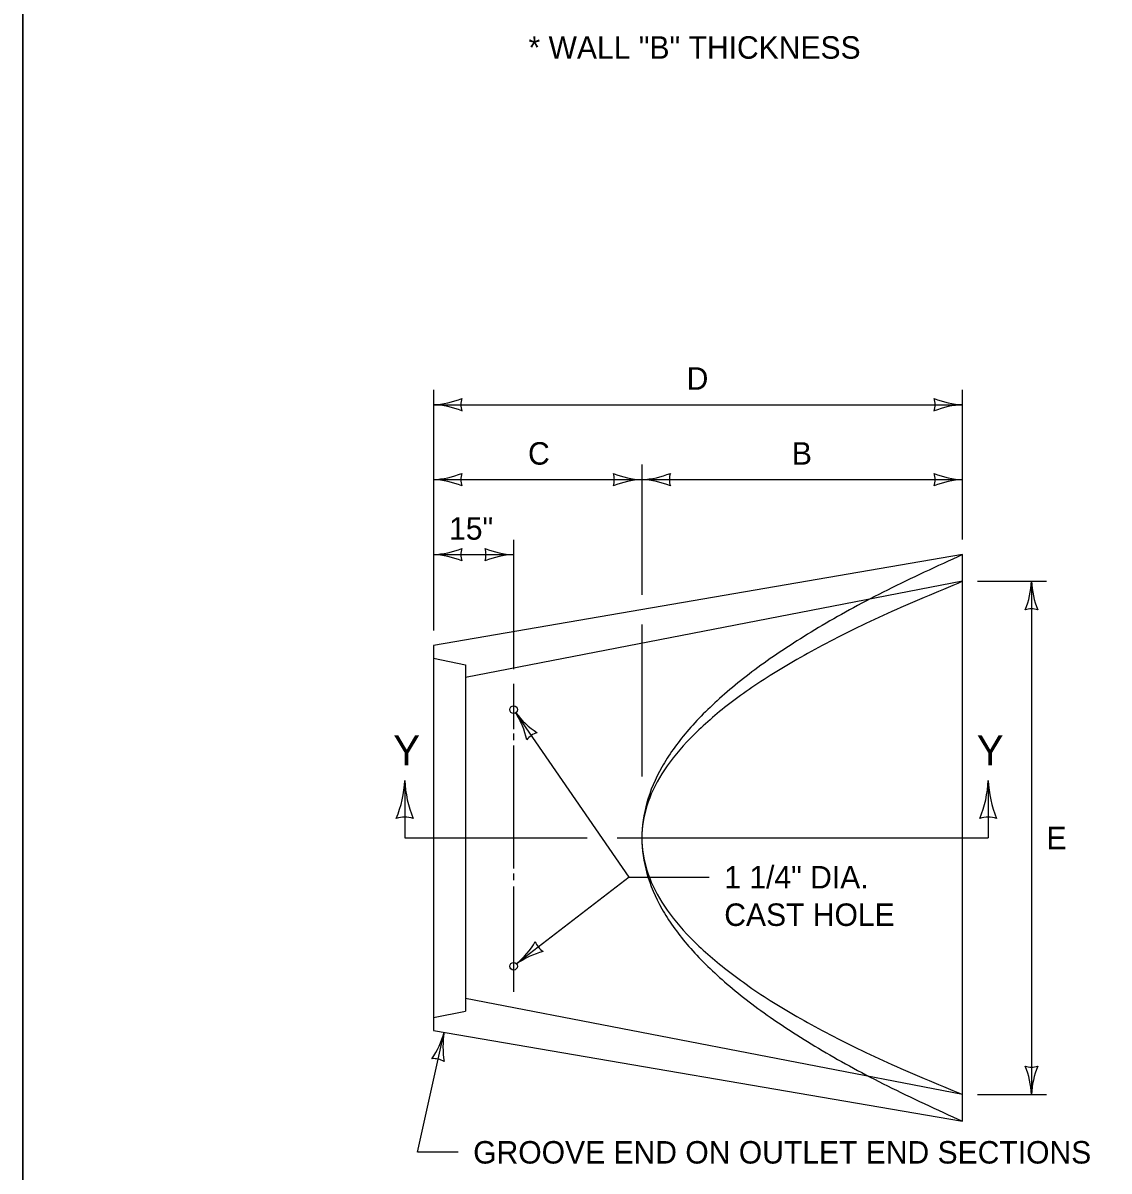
# Model space of a CAD drawing. Extents: x 49991.4 to 50021, y 49987.6 to 50011.4.
# Drawn here: x 49999.383 to 50002.282, y 49989.878 to 49992.942 of the extents above; entities that cross this region are included whole.
import ezdxf

# ---------------------------------------------------------------- set-up
doc = ezdxf.new("R2010")
doc.units = 0
for name, color, linetype in [('Level 1', 7, 'Continuous'), ('Level 2', 7, 'Continuous'), ('Level 3', 7, 'Continuous'), ('Level 4', 7, 'Continuous'), ('Level 5', 7, 'Continuous'), ('Level 6', 7, 'Continuous')]:
    doc.layers.add(name, color=color, linetype=linetype)

msp = doc.modelspace()

# ---------------------------------------------------------------- linework, layer by layer
at = {"layer": 'Level 1'}
for p, q in [((50001.8913, 49991.5236), (50000.4787, 49991.281)), ((50001.8913, 49990.011), (50001.8913, 49991.5236)), ((50000.4787, 49991.281), (50000.4787, 49990.2536)), ((50000.4787, 49990.2536), (50001.8913, 49990.011))]:
    msp.add_line(p, q, dxfattribs=at)
msp.add_lwpolyline([(49999.3835, 49998.9992), (50016.7501, 49998.9992), (50016.7501, 49987.7988), (49999.3835, 49987.7988)], close=True, dxfattribs=at)
for centre in [(50000.6927, 49991.1097), (50000.6927, 49990.4248)]:
    msp.add_circle(centre, 0.0102, dxfattribs=at)
for points in [[(50001.8913, 49991.5236), (50000.179, 49990.7673), (50001.8913, 49990.011)], [(50001.8913, 49991.4522), (50000.179, 49990.7673), (50001.8913, 49990.0823)]]:
    msp.add_open_spline(points, degree=2, dxfattribs=at)
at = {"layer": 'Level 2'}
msp.add_line((49999.3835, 49998.9992), (49999.3835, 49987.7988), dxfattribs=at)
at = {"layer": 'Level 3'}
for p, q in [((50000.4787, 49991.9636), (50000.4787, 49991.321)), ((50001.8913, 49991.5636), (50001.8913, 49991.9636)), ((50000.4787, 49991.9236), (50001.8913, 49991.9236)), ((50001.0352, 49991.7636), (50001.0352, 49991.4166)), ((50000.4787, 49991.7236), (50001.0352, 49991.7236)), ((50001.0352, 49991.7236), (50001.8913, 49991.7236)), ((50000.6927, 49991.5634), (50000.6927, 49991.3207)), ((50000.4787, 49991.5234), (50000.6927, 49991.5234)), ((50001.9313, 49991.4522), (50002.115, 49991.4522)), ((50002.075, 49991.4522), (50002.075, 49990.0823)), ((50001.0352, 49991.3366), (50001.0352, 49991.258)), ((50000.6927, 49991.3207), (50000.6927, 49991.2182)), ((50001.0352, 49991.258), (50001.0352, 49990.9309)), ((50001.0014, 49990.6625), (50000.6985, 49991.1013)), ((50001.0014, 49990.6625), (50000.7008, 49990.431)), ((50001.0014, 49990.6625), (50001.2151, 49990.6625)), ((50000.4364, 49989.9283), (50000.5077, 49990.2486)), ((50001.9313, 49990.0823), (50002.115, 49990.0823)), ((50000.545, 49989.9283), (50000.4377, 49989.9283))]:
    msp.add_line(p, q, dxfattribs=at)
for centre, radius, start, end in [((50000.4672, 49992.1563), 0.233, 272.8273, 292.0772), ((50000.4695, 49991.7015), 0.2223, 67.456, 87.6395), ((50000.6069, 49991.9236), 0.0548, 162.1388, 197.8612), ((50001.9005, 49992.1457), 0.2223, 247.456, 267.6395), ((50001.7631, 49991.9236), 0.0548, 342.1388, 17.8612), ((50001.9028, 49991.6909), 0.233, 92.8273, 112.0772), ((50000.4672, 49991.9563), 0.233, 272.8273, 292.0772), ((50000.6069, 49991.7236), 0.0548, 162.1388, 197.8612), ((50001.0444, 49991.9457), 0.2223, 247.456, 267.6395), ((50000.907, 49991.7236), 0.0548, 342.1388, 17.8612), ((50001.0237, 49991.9563), 0.233, 272.8273, 292.0772), ((50001.1634, 49991.7236), 0.0548, 162.1388, 197.8612), ((50001.9005, 49991.9457), 0.2223, 247.456, 267.6395), ((50001.7631, 49991.7236), 0.0548, 342.1388, 17.8612), ((50000.4695, 49991.5015), 0.2223, 67.456, 87.6395), ((50001.0467, 49991.4909), 0.233, 92.8273, 112.0772), ((50001.026, 49991.5015), 0.2223, 67.456, 87.6395), ((50001.9028, 49991.4909), 0.233, 92.8273, 112.0772), ((50000.4672, 49991.7561), 0.233, 272.8273, 292.0772), ((50000.4695, 49991.3013), 0.2223, 67.456, 87.6395), ((50000.6069, 49991.5234), 0.0548, 162.1388, 197.8612), ((50000.7019, 49991.7455), 0.2223, 247.456, 267.6395), ((50000.5645, 49991.5234), 0.0548, 342.1388, 17.8612), ((50000.7042, 49991.2907), 0.233, 92.8273, 112.0772), ((50001.8529, 49991.4614), 0.2223, 337.456, 357.6395), ((50002.3077, 49991.4637), 0.233, 182.8273, 202.0772), ((50002.075, 49991.324), 0.0548, 72.1388, 107.8612), ((50000.5105, 49990.9827), 0.2223, 12.073, 32.2565), ((50000.8835, 49991.243), 0.233, 217.4443, 236.6942), ((50000.7713, 49990.9958), 0.0548, 106.7558, 142.4782), ((50000.1061, 49990.9332), 0.2964, 337.456, 357.6395), ((50000.7126, 49990.9363), 0.3107, 182.8273, 202.0772), ((50001.6633, 49990.9332), 0.2964, 337.456, 357.6395), ((50002.2698, 49990.9363), 0.3107, 182.8273, 202.0772), ((50000.4023, 49990.75), 0.073, 72.1388, 107.8612), ((50001.9595, 49990.75), 0.073, 72.1388, 107.8612), ((50000.5497, 49990.6084), 0.233, 310.4281, 329.678), ((50000.8024, 49990.5092), 0.0548, 199.7396, 235.462), ((50000.8291, 49990.2494), 0.2223, 105.0568, 125.2403), ((50000.2928, 49990.3058), 0.2223, 324.9059, 345.0894), ((50000.7373, 49990.2093), 0.233, 170.2772, 189.5271), ((50000.4798, 49990.1235), 0.0548, 59.5887, 95.3111), ((50002.075, 49990.2105), 0.0548, 252.1388, 287.8612), ((50001.8423, 49990.0708), 0.233, 2.8273, 22.0772), ((50002.2971, 49990.0731), 0.2223, 157.456, 177.6395)]:
    msp.add_arc(centre, radius, start, end, dxfattribs=at)
at = {"layer": 'Level 4'}
for p, q in [((50001.8913, 49991.4522), (50000.5642, 49991.1953)), ((50000.4787, 49991.2467), (50000.5642, 49991.2296)), ((50000.5642, 49991.2296), (50000.5642, 49990.305)), ((50001.8913, 49990.0823), (50000.5642, 49990.3392)), ((50000.4787, 49990.2878), (50000.5642, 49990.305))]:
    msp.add_line(p, q, dxfattribs=at)
at = {"layer": 'Level 5'}
for p, q in [((50000.6927, 49991.1782), (50000.6927, 49991.058)), ((50000.6927, 49991.0464), (50000.6927, 49991.0281)), ((50000.6927, 49991.0142), (50000.6927, 49990.6861)), ((50000.6927, 49990.6723), (50000.6927, 49990.655)), ((50000.6927, 49990.6377), (50000.6927, 49990.3563))]:
    msp.add_line(p, q, dxfattribs=at)
at = {"layer": 'Level 6'}
for p, q in [((50000.4023, 49990.921), (50000.4023, 49990.7673)), ((50001.9595, 49990.921), (50001.9595, 49990.7673)), ((50000.4023, 49990.7673), (50000.8891, 49990.7673)), ((50000.9691, 49990.7673), (50001.9595, 49990.7673))]:
    msp.add_line(p, q, dxfattribs=at)

# ---------------------------------------------------------------- texts
at = {"layer": 'Level 2'}
for s, height, p in [('* WALL "B" THICKNESS', 0.06, (50000.7327, 49992.847)), ('D', 0.06, (50001.1547, 49991.9636)), ('C', 0.06, (50000.7314, 49991.7636)), ('B', 0.06, (50001.4355, 49991.7636)), ('15"', 0.06, (50000.5207, 49991.5634)), ('Y', 0.08, (50000.3718, 49990.961)), ('Y', 0.08, (50001.929, 49990.961)), ('E', 0.06, (50002.115, 49990.7373)), ('1 1/4" DIA.', 0.06, (50001.2551, 49990.6325)), ('CAST HOLE', 0.06, (50001.2551, 49990.5325)), ('GROOVE END ON OUTLET END SECTIONS', 0.06, (50000.585, 49989.8983))]:
    msp.add_text(s, height=height, dxfattribs=at).set_placement(p)

doc.saveas('drawing.dxf')
